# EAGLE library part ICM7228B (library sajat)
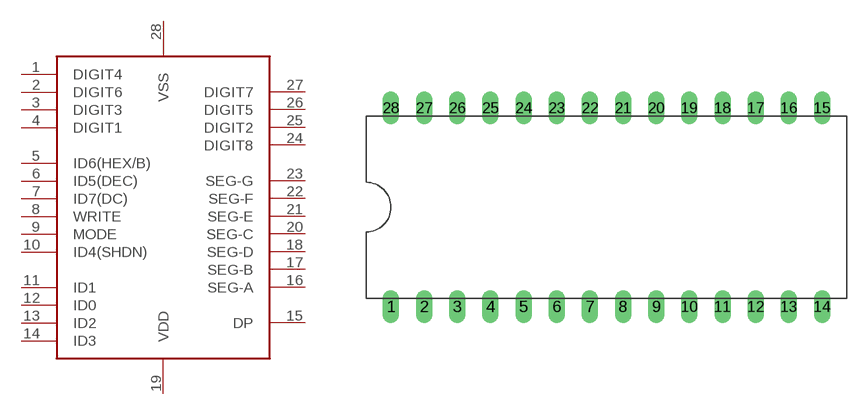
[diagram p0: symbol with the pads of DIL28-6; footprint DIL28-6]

Designator prefix -

## ICM7228B  [DIL28-6]
1  DIGIT4  out
2  DIGIT6  out
3  DIGIT3  out
4  DIGIT1  out
5  ID6(HEX/B)  in
6  ID5(DEC)  in
7  ID7(DC)  in
8  WRITE  in
9  MODE  in
10  ID4(SHDN)  in
11  ID1  in
12  ID0  in
13  ID2  in
14  ID3  in
15  DP  out
16  SEG-A  out
17  SEG-B  out
18  SEG-D  out
19  VDD  pwr
20  SEG-C  out
21  SEG-E  out
22  SEG-F  out
23  SEG-G  out
24  DIGIT8  out
25  DIGIT2  out
26  DIGIT5  out
27  DIGIT7  out
28  VSS  pwr

## Footprint DIL28-6 (pad centres in mm)
drill 0.3 pad 1.27 long: 1 -16.51,-7.62; 2 -13.97,-7.62; 3 -11.43,-7.62; 4 -8.89,-7.62; 5 -6.35,-7.62; 6 -3.81,-7.62; 7 -1.27,-7.62; 8 1.27,-7.62; 9 3.81,-7.62; 10 6.35,-7.62; 11 8.89,-7.62; 12 11.43,-7.62; 13 13.97,-7.62; 14 16.51,-7.62; 15 16.51,7.62; 16 13.97,7.62; 17 11.43,7.62; 18 8.89,7.62; 19 6.35,7.62; 20 3.81,7.62; 21 1.27,7.62; 22 -1.27,7.62; 23 -3.81,7.62; 24 -6.35,7.62; 25 -8.89,7.62; 26 -11.43,7.62; 27 -13.97,7.62; 28 -16.51,7.62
